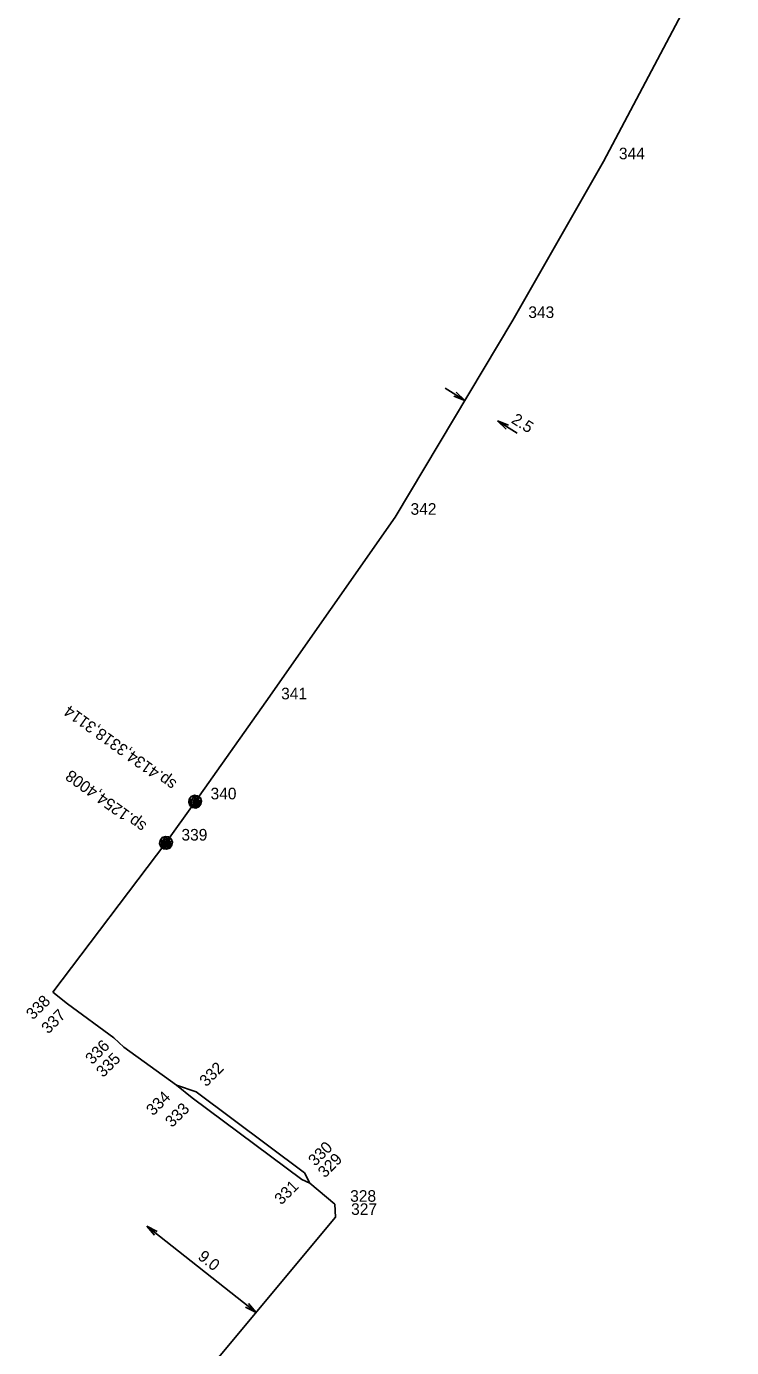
# Model space of a CAD drawing. Extents: x -535557 to -534097, y -1142175 to -1136716.
# Drawn here: x -534593.2 to -534547.6, y -1141509.9 to -1141424.6 of the extents above; entities that cross this region are included whole.
import ezdxf

# ---------------------------------------------------------------- set-up
doc = ezdxf.new("R2010")
doc.units = 0
doc.layers.add('Default', color=7, linetype='Continuous')
doc.layers.add('SS_SZDC', color=7, linetype='Continuous')

# ---------------------------------------------------------------- blocks, each defined once
blk = doc.blocks.new('POINT_DISPLAY')
at = {"layer": 'Default'}
blk.add_line((0, 0), (0, 0), dxfattribs=at)

msp = doc.modelspace()

# ---------------------------------------------------------------- linework, layer by layer
at = {"layer": 'SS_SZDC'}
for p, q in [((-534555.909, -1141433.29), (-534547.63, -1141417.629)), ((-534561.76, -1141443.54), (-534555.909, -1141433.29)), ((-534569.369, -1141456.25), (-534561.76, -1141443.54)), ((-534564.859, -1141448.717), (-534566.13, -1141447.92)), ((-534564.859, -1141448.717), (-534565.574, -1141448.445)), ((-534565.415, -1141448.191), (-534564.859, -1141448.717)), ((-534562.751, -1141450.04), (-534561.481, -1141450.837)), ((-534562.196, -1141450.565), (-534562.751, -1141450.04)), ((-534562.751, -1141450.04), (-534562.036, -1141450.311)), ((-534569.369, -1141456.25), (-534577.729, -1141468.17)), ((-534577.729, -1141468.17), (-534582.289, -1141474.629)), ((-534582.67, -1141474.471), (-534582.541, -1141474.288)), ((-534582.541, -1141474.288), (-534582.328, -1141474.219)), ((-534582.532, -1141474.896), (-534582.45, -1141474.352)), ((-534582.45, -1141474.352), (-534582.336, -1141474.268)), ((-534582.336, -1141474.268), (-534582.441, -1141474.961)), ((-534582.342, -1141474.976), (-534582.237, -1141474.283)), ((-534582.328, -1141474.219), (-534582.131, -1141474.249)), ((-534582.243, -1141474.991), (-534582.138, -1141474.298)), ((-534582.138, -1141474.298), (-534582.054, -1141474.412)), ((-534582.054, -1141474.412), (-534582.137, -1141474.956)), ((-534582.131, -1141474.249), (-534581.948, -1141474.378)), ((-534581.948, -1141474.378), (-534581.879, -1141474.591)), ((-534584.17, -1141477.29), (-534582.289, -1141474.629)), ((-534582.7, -1141474.668), (-534582.67, -1141474.471)), ((-534582.631, -1141474.881), (-534582.7, -1141474.668)), ((-534582.448, -1141475.01), (-534582.631, -1141474.881)), ((-534582.564, -1141474.436), (-534582.609, -1141474.733)), ((-534582.609, -1141474.733), (-534582.532, -1141474.896)), ((-534582.251, -1141475.04), (-534582.448, -1141475.01)), ((-534582.441, -1141474.961), (-534582.243, -1141474.991)), ((-534582.038, -1141474.971), (-534582.251, -1141475.04)), ((-534582.137, -1141474.956), (-534582.015, -1141474.823)), ((-534581.909, -1141474.788), (-534582.038, -1141474.971)), ((-534582.015, -1141474.823), (-534581.97, -1141474.526)), ((-534581.879, -1141474.591), (-534581.909, -1141474.788)), ((-534584.55, -1141477.131), (-534584.421, -1141476.948)), ((-534584.421, -1141476.948), (-534584.208, -1141476.879)), ((-534584.33, -1141477.012), (-534584.216, -1141476.928)), ((-534584.216, -1141476.928), (-534584.321, -1141477.621)), ((-534584.222, -1141477.636), (-534584.117, -1141476.943)), ((-534584.208, -1141476.879), (-534584.011, -1141476.909)), ((-534584.123, -1141477.651), (-534584.018, -1141476.958)), ((-534584.018, -1141476.958), (-534583.934, -1141477.072)), ((-534584.011, -1141476.909), (-534583.828, -1141477.038)), ((-534591.47, -1141486.94), (-534584.17, -1141477.29)), ((-534584.58, -1141477.328), (-534584.55, -1141477.131)), ((-534584.511, -1141477.541), (-534584.58, -1141477.328)), ((-534584.328, -1141477.67), (-534584.511, -1141477.541)), ((-534584.444, -1141477.096), (-534584.489, -1141477.393)), ((-534584.489, -1141477.393), (-534584.412, -1141477.556)), ((-534584.412, -1141477.556), (-534584.33, -1141477.012)), ((-534584.131, -1141477.7), (-534584.328, -1141477.67)), ((-534584.321, -1141477.621), (-534584.123, -1141477.651)), ((-534583.918, -1141477.631), (-534584.131, -1141477.7)), ((-534583.934, -1141477.072), (-534584.017, -1141477.616)), ((-534584.017, -1141477.616), (-534583.895, -1141477.483)), ((-534583.789, -1141477.448), (-534583.918, -1141477.631)), ((-534583.895, -1141477.483), (-534583.85, -1141477.186)), ((-534583.828, -1141477.038), (-534583.759, -1141477.251)), ((-534583.759, -1141477.251), (-534583.789, -1141477.448)), ((-534590.539, -1141487.68), (-534591.47, -1141486.94)), ((-534587.529, -1141489.879), (-534590.539, -1141487.68)), ((-534586.899, -1141490.489), (-534587.529, -1141489.879)), ((-534583.5, -1141492.94), (-534586.899, -1141490.489)), ((-534582.21, -1141493.379), (-534583.5, -1141492.94)), ((-534583.5, -1141492.94), (-534582.479, -1141493.76)), ((-534582.479, -1141493.76), (-534575.39, -1141499.04)), ((-534575.22, -1141498.6), (-534582.21, -1141493.379)), ((-534574.88, -1141499.27), (-534575.39, -1141499.04)), ((-534574.88, -1141499.27), (-534575.22, -1141498.6)), ((-534573.27, -1141500.62), (-534574.88, -1141499.27)), ((-534573.21, -1141501.469), (-534573.27, -1141500.62)), ((-534582.899, -1141513.069), (-534573.21, -1141501.469)), ((-534578.343, -1141507.615), (-534585.415, -1141502.039)), ((-534584.919, -1141502.621), (-534585.415, -1141502.039)), ((-534585.415, -1141502.039), (-534584.733, -1141502.385)), ((-534578.343, -1141507.615), (-534579.025, -1141507.268)), ((-534578.839, -1141507.033), (-534578.343, -1141507.615))]:
    msp.add_line(p, q, dxfattribs=at)

# ---------------------------------------------------------------- block references
for p in [(-534555.909, -1141433.29), (-534561.76, -1141443.54), (-534569.369, -1141456.25), (-534577.729, -1141468.17), (-534582.289, -1141474.629), (-534584.17, -1141477.29), (-534591.47, -1141486.94), (-534590.539, -1141487.68), (-534587.529, -1141489.879), (-534586.899, -1141490.489), (-534583.5, -1141492.94), (-534582.479, -1141493.76), (-534582.21, -1141493.379), (-534575.39, -1141499.04), (-534575.22, -1141498.6), (-534574.88, -1141499.27), (-534573.27, -1141500.62), (-534573.21, -1141501.469)]:
    msp.add_blockref('POINT_DISPLAY', p, dxfattribs=at)

# ---------------------------------------------------------------- texts
for s, p in [('344', (-534554.909, -1141433.14)), ('343', (-534560.76, -1141443.39)), ('342', (-534568.369, -1141456.099)), ('341', (-534576.729, -1141468.02)), ('340', (-534581.289, -1141474.479)), ('339', (-534583.17, -1141477.14)), ('328', (-534572.27, -1141500.47)), ('327', (-534572.21, -1141501.319))]:
    msp.add_text(s, height=0.75, dxfattribs=at).set_placement(p)
for s, height, rotation, p in [('2.5', 0.75, 327.89287, (-534561.917, -1141450.121)), ('sp.4134,3318,3114', 0.74999, 144.37566, (-534583.425, -1141473.361)), ('sp.1254,4008', 0.74999, 144.37566, (-534585.368, -1141476.074)), ('338', 0.75, 45, (-534592.763, -1141488.759)), ('337', 0.75, 45, (-534591.774, -1141489.671)), ('336', 0.75, 45, (-534588.935, -1141491.65)), ('335', 0.75, 45, (-534588.232, -1141492.483)), ('332', 0.75, 45, (-534581.564, -1141493.082)), ('334', 0.75, 45, (-534585.002, -1141494.958)), ('333', 0.75, 45, (-534583.778, -1141495.713)), ('330', 0.75, 45, (-534574.533, -1141498.213)), ('329', 0.75, 45, (-534573.908, -1141498.968)), ('331', 0.75, 45, (-534576.72, -1141500.713)), ('9.0', 0.75, 321.74558, (-534582.166, -1141504.123))]:
    msp.add_text(s, height=height, rotation=rotation, dxfattribs=at).set_placement(p)

doc.saveas('drawing.dxf')
